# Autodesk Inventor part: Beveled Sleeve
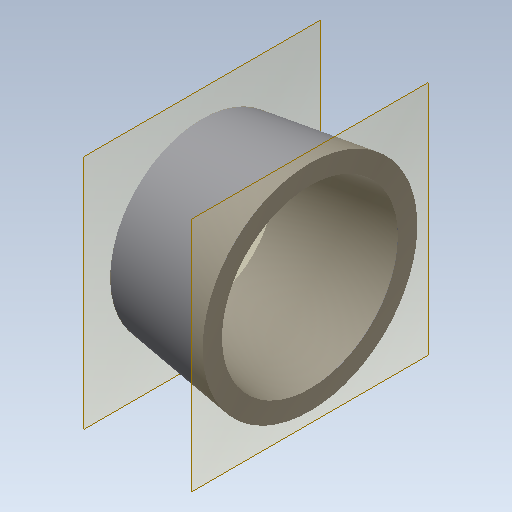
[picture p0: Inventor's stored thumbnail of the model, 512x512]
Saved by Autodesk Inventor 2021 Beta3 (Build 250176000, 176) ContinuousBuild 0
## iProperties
Created: 2012-08
Part Number: Beveled Sleeve
Material: Generic
Document SubType Name: Modeling
Designer: John
Density: 1 g/cm^3
Appearance: Default
Author: John
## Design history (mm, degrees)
sketch "Sketch1"
  geometry: C1 r 4.826 at (0, 0); 1 further point
  constraints: 1 centre point, 1 coincident
  dimensions: "d0" = 9.652 diameter of C1
workplane "Work Plane1"
sketch "Sketch2"
  geometry: C1 r 4.128 at (0, 0); 1 further point
  constraints: 1 centre point, 1 coincident
  dimensions: "d2" = 8.255 diameter of C1
loft "Loft1" sketch "Sketch2" dims "d3" = 0, "d4" = 90 deg, "d5" = 0, "d6" = 90 deg
shell "Shell1" dims "d7" = 0.8636
body "Solid1"
other parameters: "d1" = -4.8514
